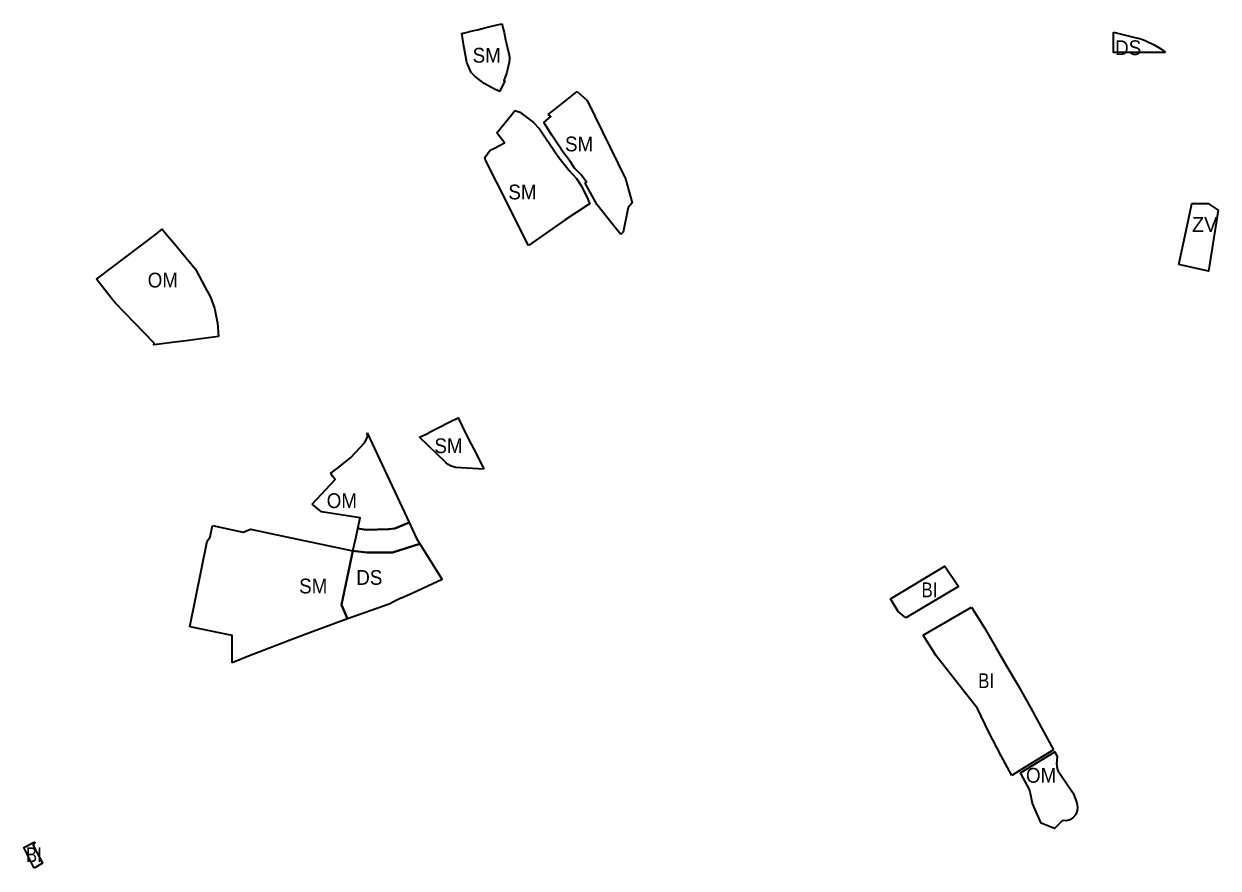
# Model space of a CAD drawing. Extents: x -650971 to -642489, y -1074311 to -1062745.
# Drawn here: x -647339 to -646370, y -1071700 to -1071015 of the extents above; entities that cross this region are included whole.
import ezdxf

# ---------------------------------------------------------------- set-up
doc = ezdxf.new("R2010")
doc.units = 0
doc.header["$LTSCALE"] = 4.8
for name, color, linetype, lineweight in [('12', 7, 'Continuous', 35), ('15', 7, 'Continuous', 35), ('18', 7, 'Continuous', 35), ('2', 7, 'Continuous', 35), ('24', 7, 'Continuous', 35), ('40', 7, 'Continuous', 35), ('62', 7, 'Continuous', 35)]:
    doc.layers.add(name, color=color, linetype=linetype, lineweight=lineweight)

msp = doc.modelspace()

# ---------------------------------------------------------------- linework, layer by layer
at = {"layer": '12'}
msp.add_line((-647280.14, -1071221.92), (-647231.69, -1071185.15), dxfattribs=at)
for points in [[(-647231.69, -1071185.15), (-647226.895, -1071181.511), (-647223.46, -1071185.83)], [(-647223.46, -1071185.83), (-647216.8, -1071193.7), (-647207.67, -1071204.52), (-647199.82, -1071213.98)], [(-647199.82, -1071213.98), (-647192.29, -1071228.1), (-647187.68, -1071236.74), (-647184.58, -1071245.67), (-647181.99, -1071257.66), (-647181.12, -1071268.66)], [(-647181.12, -1071268.66), (-647209.66, -1071272.22), (-647214.45, -1071272.79), (-647218.75, -1071273.32), (-647227.29, -1071274.42), (-647233.64, -1071275.42), (-647233.34, -1071274.07), (-647265.15, -1071241.1), (-647268.52, -1071236.78), (-647280.14, -1071221.92)], [(-647105.2, -1071404.54), (-647086.45, -1071384.59), (-647088.57, -1071381.97), (-647090.04, -1071379.44), (-647083.48, -1071374.62), (-647073.68, -1071366.75), (-647062.78, -1071354.77), (-647061.4, -1071352.51), (-647060.22, -1071349.87), (-647060.6, -1071346.87)], [(-647060.6, -1071346.87), (-647056.48, -1071355.32), (-647030.23, -1071411.53), (-647026.472, -1071419.614)], [(-647068.162, -1071424.298), (-647066.35, -1071415.79), (-647097.5, -1071410.96), (-647105.2, -1071404.54)], [(-647026.472, -1071419.614), (-647038.119, -1071424.37), (-647043.137, -1071424.978), (-647061.23, -1071425.434), (-647068.162, -1071424.298)]]:
    msp.add_lwpolyline(points, dxfattribs=at)
msp.add_lwpolyline([(-646500.83, -1071615.62), (-646500.793, -1071616.359), (-646500.721, -1071617.099), (-646500.612, -1071617.835), (-646500.468, -1071618.567), (-646500.289, -1071619.291), (-646500.076, -1071620.004), (-646499.829, -1071620.704), (-646499.55, -1071621.39), (-646497.83, -1071624.02), (-646487.56, -1071639.23), (-646486.31, -1071641.97), (-646485.2, -1071644.85), (-646484.38, -1071647.41), (-646483.97, -1071650.63), (-646484.15, -1071653.38), (-646485.29, -1071656.53), (-646487.36, -1071659.1), (-646490.07, -1071660.88), (-646492.89, -1071661.75), (-646496.06, -1071661.5), (-646502.53, -1071667.82), (-646513.43, -1071663.64), (-646520.32, -1071647.59), (-646522, -1071639.62), (-646522.99, -1071636.22), (-646530.27, -1071622.79), (-646502.39, -1071605.72), (-646500.34, -1071609.66)], close=True, dxfattribs=at)
at = {"layer": '15'}
for points in [[(-647072.11, -1071442.6), (-647069.87, -1071432.32), (-647068.162, -1071424.298)], [(-647068.162, -1071424.298), (-647061.23, -1071425.434), (-647043.137, -1071424.978), (-647038.119, -1071424.37), (-647026.472, -1071419.614)], [(-647026.472, -1071419.614), (-647020.52, -1071432.42), (-647017.7, -1071436.79)], [(-647017.7, -1071436.79), (-647040.089, -1071443.76), (-647060.812, -1071444.006), (-647072.11, -1071442.6)]]:
    msp.add_lwpolyline(points, dxfattribs=at)
at = {"layer": '18'}
msp.add_line((-647204.42, -1071504.1), (-647190.4, -1071434.75), dxfattribs=at)
for points in [[(-646983.66, -1071022.3), (-646982.41, -1071022.23), (-646973.85, -1071020.2), (-646970.88, -1071019.5), (-646968.01, -1071018.82), (-646967.03, -1071018.58), (-646964.89, -1071018.08), (-646955.09, -1071015.67), (-646951.06, -1071014.78)], [(-646951.06, -1071014.78), (-646950.88, -1071015.45), (-646950.1, -1071018.82), (-646949.39, -1071021.83), (-646948.89, -1071024.84), (-646948.18, -1071027.86), (-646947.45, -1071030.92), (-646946.03, -1071036.96), (-646945.33, -1071039.92), (-646944.88, -1071042.78), (-646945.38, -1071045.82), (-646946.7, -1071051.77), (-646947.41, -1071054.95), (-646949.48, -1071060.79), (-646948.83, -1071061.12), (-646950.25, -1071064.1), (-646952.2, -1071068.17), (-646952.75, -1071069.62)], [(-646972.78, -1071057.43), (-646974.79, -1071055.48), (-646976.03, -1071054.29), (-646979.75, -1071046.19), (-646981.87, -1071034.13), (-646982.08, -1071032.76), (-646983.66, -1071022.3)], [(-646952.75, -1071069.62), (-646956.66, -1071067.91), (-646965.69, -1071063.05), (-646972.78, -1071057.43)], [(-646913.49, -1071088.22), (-646906.17, -1071082.72), (-646890.12, -1071069.67)], [(-646890.12, -1071069.67), (-646881.89, -1071077.03), (-646850.93, -1071140.54), (-646845.39, -1071159.98), (-646848.58, -1071163.95), (-646852.86, -1071183.98), (-646854.49, -1071185.87)], [(-646929.64, -1071194.58), (-646955.2, -1071143.67), (-646964.43, -1071125.3), (-646964.99, -1071123.18), (-646960.72, -1071117.25), (-646957.26, -1071115.61), (-646949.12, -1071111.22), (-646955.39, -1071103.23), (-646943.47, -1071088.69), (-646940.67, -1071085.15)], [(-646940.67, -1071085.15), (-646936.51, -1071086.33), (-646925.88, -1071094.68), (-646920.54, -1071099.98), (-646906.72, -1071120.46), (-646904.64, -1071123.54), (-646896.62, -1071133.93), (-646890.59, -1071140.39), (-646887.07, -1071145.66), (-646881.97, -1071155.84), (-646879.91, -1071161.24)], [(-646917.04, -1071094.75), (-646911.58, -1071089.9), (-646913.49, -1071088.22)], [(-646854.49, -1071185.87), (-646861.58, -1071177.05), (-646873.89, -1071161.58), (-646883.63, -1071144.15), (-646882.37, -1071143.39), (-646886.78, -1071137.25), (-646892.11, -1071131.81), (-646895.56, -1071126.84), (-646902.62, -1071117.58), (-646902.39, -1071117.39), (-646910.53, -1071105.18), (-646915.15, -1071097.91), (-646917.04, -1071094.75)], [(-646879.91, -1071161.24), (-646881.68, -1071161.83), (-646899.85, -1071173.89), (-646929.64, -1071194.58)], [(-647017.93, -1071350.33), (-647013.15, -1071348.01), (-647010.49, -1071346.63), (-647009.82, -1071346.28), (-647004.02, -1071343.32), (-647003.37, -1071342.99), (-646993.38, -1071337.85), (-646986.69, -1071334.53), (-646983.33, -1071341.44), (-646977.95, -1071352.38), (-646974.28, -1071359.48), (-646968.63, -1071370.46), (-646965.74, -1071376.18)], [(-646965.74, -1071376.18), (-646988.77, -1071374.77), (-646992.95, -1071373.61), (-646994.85, -1071372.49), (-646996.58, -1071370.92), (-647017.93, -1071350.33)], [(-647190.4, -1071434.75), (-647187.94, -1071431.16), (-647185.99, -1071421.98)], [(-647185.99, -1071421.98), (-647161.2, -1071427.33), (-647155.36, -1071425), (-647126.02, -1071431.21), (-647072.11, -1071442.6)], [(-647072.11, -1071442.6), (-647081.488, -1071486.251), (-647076.46, -1071497.69)], [(-647170.23, -1071533.44), (-647170.18, -1071532.22), (-647170.01, -1071511.22), (-647172.85, -1071510.64), (-647202.85, -1071504.42), (-647204.42, -1071504.1)], [(-647076.46, -1071497.69), (-647104.47, -1071508.08), (-647123.17, -1071515.01), (-647151.28, -1071525.99), (-647155.58, -1071527.62), (-647170.23, -1071533.44)]]:
    msp.add_lwpolyline(points, dxfattribs=at)
at = {"layer": '2'}
msp.add_line((-646609.21, -1071510.98), (-646570, -1071488.38), dxfattribs=at)
for points in [[(-646635.79, -1071481.6), (-646591.65, -1071454.91), (-646580.58, -1071471.48), (-646623.18, -1071496.99)], [(-646623.18, -1071496.99), (-646629.37, -1071491.74), (-646635.79, -1071481.6)], [(-646570, -1071488.38), (-646559.53, -1071505.12), (-646550.23, -1071520.88), (-646541.14, -1071536.3), (-646532.04, -1071551.72), (-646521.8, -1071570.34), (-646511.47, -1071589.11), (-646503.31, -1071603.95)], [(-646537.28, -1071624.8), (-646545.89, -1071609.07), (-646555.78, -1071589.66), (-646565.17, -1071570.4), (-646598.63, -1071527.8), (-646609.21, -1071510.98)], [(-646503.31, -1071603.95), (-646531.2, -1071621.07), (-646537.28, -1071624.8)], [(-647330.73, -1071700.09), (-647339.211, -1071683.431), (-647330.34, -1071678.82)], [(-647330.34, -1071678.82), (-647331.65, -1071681.7), (-647324.21, -1071696.2), (-647330.73, -1071700.09)]]:
    msp.add_lwpolyline(points, dxfattribs=at)
at = {"layer": '24'}
for points in [[(-646454.59, -1071021.54), (-646436.15, -1071025.97), (-646434.39, -1071026.41), (-646430.91, -1071027.44), (-646427.84, -1071028.9), (-646421.58, -1071031.81), (-646415.61, -1071035.4), (-646412.54, -1071038.01)], [(-646412.54, -1071038.01), (-646454.59, -1071038), (-646454.59, -1071021.54)], [(-647072.11, -1071442.6), (-647060.812, -1071444.006), (-647040.089, -1071443.76), (-647017.7, -1071436.79), (-646999.77, -1071465.81)], [(-647076.46, -1071497.69), (-647081.488, -1071486.251), (-647072.11, -1071442.6)], [(-646999.77, -1071465.81), (-647022.81, -1071476.61), (-647032.73, -1071480.88), (-647033.09, -1071481.06), (-647038.62, -1071483.74), (-647042.78, -1071485.76), (-647076.46, -1071497.69)]]:
    msp.add_lwpolyline(points, dxfattribs=at)
at = {"layer": '40'}
msp.add_line((-646401.64, -1071210.18), (-646394.05, -1071174.83), dxfattribs=at)
msp.add_lwpolyline([(-646394.05, -1071174.83), (-646391.07, -1071160.52), (-646377.87, -1071160.66), (-646369.76, -1071166.06), (-646377.5, -1071215.56), (-646401.64, -1071210.18)], dxfattribs=at)

# ---------------------------------------------------------------- texts
at = {"layer": '62'}
for s, width, p in [('DS', 0.95, (-646453.386, -1071040.148)), ('SM', 0.95, (-646974.938, -1071046.245)), ('SM', 0.95, (-646899.938, -1071118.245)), ('SM', 0.95, (-646945.938, -1071157.245)), ('OM', 0.95, (-647238.703, -1071228.756)), ('SM', 0.95, (-647005.938, -1071363.245)), ('OM', 0.95, (-647093.38, -1071407.817)), ('SM', 0.95, (-647115.735, -1071477.109)), ('DS', 0.95, (-647069.386, -1071470.148)), ('BI', 0.85, (-646610.515, -1071480.22)), ('BI', 0.85, (-646564.529, -1071553.971)), ('OM', 0.95, (-646525.703, -1071630.756)), ('BI', 0.85, (-647337.578, -1071695.247))]:
    msp.add_text(s, height=12, dxfattribs=dict(at, width=width)).set_placement(p)
msp.add_text('ZV', height=12, dxfattribs=at).set_placement((-646390.931, -1071183.591))

doc.saveas('drawing.dxf')
